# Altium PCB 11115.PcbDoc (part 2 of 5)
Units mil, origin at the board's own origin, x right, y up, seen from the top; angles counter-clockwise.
Board outline 4800 x 3500.1 mil, 4 copper layers (Top Layer, Layer 2, Layer 3, Bottom Layer), stack 61.6 mil thick; 316 components, 224 nets, 954 pads, 623 vias.
Unrouted connection lines stored in the file: 268.
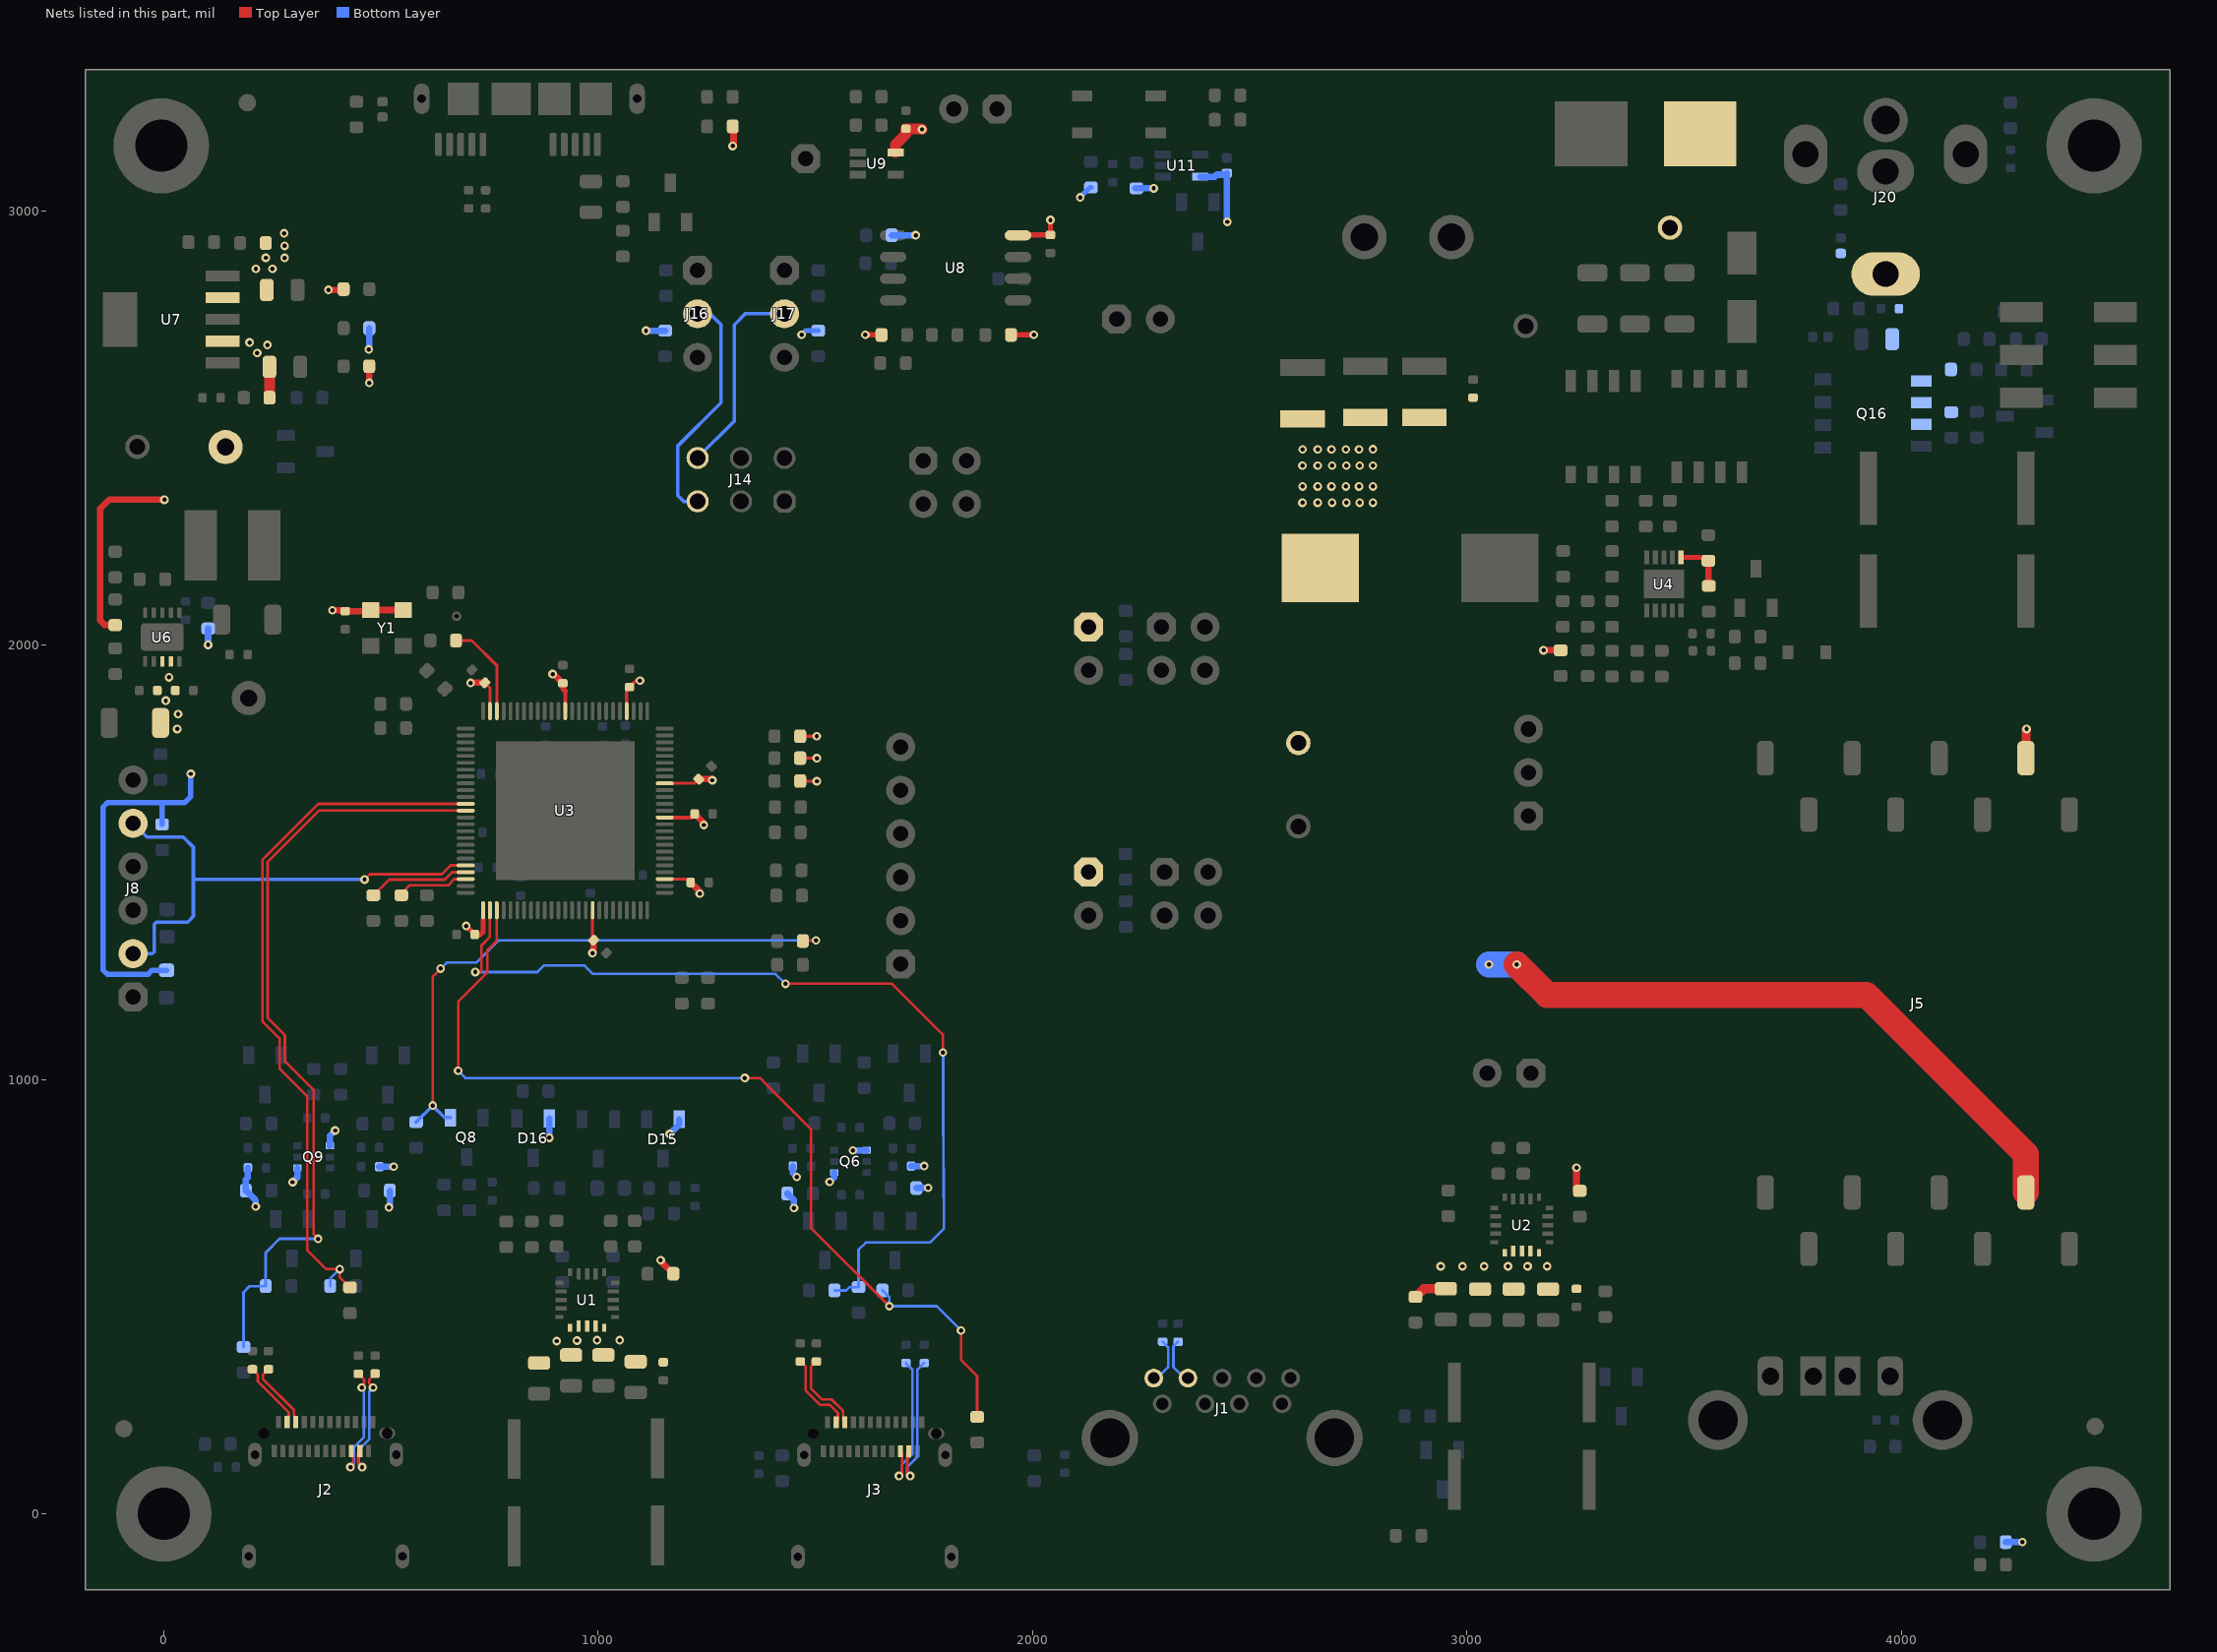
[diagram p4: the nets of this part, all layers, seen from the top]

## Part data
C1 C2 C3 C4: library part CAP1298, "Capacitor", Manufacturer 1="Panasonic Electronic Components", Manufacturer Part Number 1=EEE-FPC151XAP, Operating Temperature="-55C to 105C", Package=D8, Supplier Part Number 1=PCE4535CT-ND, Tolerance=20%, Voltage=16V
C5 C6 C7 C8 C16 C17 C18 C19: library part CAP0646, "Capacitor", Manufacturer 1="Taiyo Yuden", Manufacturer Part Number 1=JMK212BJ476MG-T, Operating Temperature="-55C to +85C", Package=0805, Supplier Part Number 1=587-1779-1-ND, Temperature Coeffcient=X5R, Tolerance=20%, Voltage=6.3V
C9 C10 C11 C12 C13 C14 C15 C20 C21 C22 C23 C24 C25 C26 C28 C30 C31 C32 C33 C35 C36 C38 C40 C43 C49 C55 C56 C57 C58 C60 C61 C62 C63 C64 C65 C66 C67 C68 C69 C70 C71 C72 C73 C74 C75 C76 C77 C78 C79 C80 C81 C82 C83 C84 C85 C86 C87 C88 C89 C90 C91 C92 C93 C96 C100 C101: library part CAP1337, "Capacitor", Manufacturer 1="TDK Corporation", Manufacturer Part Number 1=CGA2B3X7R1V104K050BB, Operating Temperature="-55C to 125C", Package=0402, Supplier Part Number 1=445-6901-1-ND, Temperature Coeffcient=X7R, Tolerance=10%, Voltage=35V
C27 C59 C94 C95: library part CAP0373, "Capacitor", Manufacturer 1="Wurth Electronics Inc", Manufacturer 2=Murata, Manufacturer 3="Taiyo Yuden", Manufacturer Part Number 1=885012107014, Manufacturer Part Number 2=GRM21BR61C106KE15L, Manufacturer Part Number 3=EMK212BJ106KG-T, Operating Temperature="+25C to +125C", Package=0805, Supplier Part Number 1=732-7624-1-ND, Temperature Coeffcient=X5R, Tolerance=10%, Voltage=16V
C29 C37 C39: library part CAP1998, "Capacitor", Manufacturer 1="WUERTH ELEKTRONIK", Manufacturer Part Number 1=885012108022, Operating Temperature="-55C to +85C", Package=1206, Temperature Coeffcient=X5R, Tolerance=10%, Voltage=50V
C34 C97: library part CAP1259, "Capacitor", Manufacturer 1="Samsung Electro-Mechanics America, Inc", Manufacturer Part Number 1=CL31B226KPHNNNE, Operating Temperature="-55C to +125C", Package=1206, Supplier Part Number 1=1276-2769-1-ND, Temperature Coeffcient=X7R, Tolerance=10%, Voltage=10V
C41 C42: library part CAP2007, "Capacitor", Manufacturer 1=KEMET, Manufacturer Part Number 1=EDT476M050S9MAA, Operating Temperature="-40°C ~ 125°C", Package=F, Supplier Part Number 1=80-EDT476M050S9MAA, Tolerance=20%, Voltage=50V
C44 C45: library part CAP2214, "Capacitor", Manufacturer 1="TDK Corporation", Manufacturer Part Number 1=CGA3E3X7R1H334K080AB, Operating Temperature="-55°C ~ 125°C", Package=0603, Supplier Part Number 1=445-174426-1-ND, Temperature Coeffcient=X7R, Tolerance=10%, Voltage=50V
C46 C47 C48: library part CAP0598, "Capacitor", Manufacturer 1="Taiyo Yuden", Manufacturer Part Number 1=LMK325BJ107MM-T, Operating Temperature="-55C to +85C", Package=1210, Supplier Part Number 1=587-1965-1-ND, Temperature Coeffcient=X5R, Tolerance=20%, Voltage=10V
C50: library part CAP0638, "Capacitor", Manufacturer 1="Taiyo Yuden", Manufacturer Part Number 1=LMK107BJ105KA-T, Operating Temperature="-55C to +85C", Package=0603, Supplier Part Number 1=587-2400-1-ND, Temperature Coeffcient=X5R, Tolerance=10%, Voltage=50V
C51: library part CAP1232, "Capacitor", Manufacturer 1=TDK, Manufacturer Part Number 1=C1608C0G1H392J080AA, Operating Temperature="-55C to +125C", Package=0603, Supplier Part Number 1=445-7399-1-ND, Temperature Coeffcient=C0G, Tolerance=5%, Voltage=50V
C52: library part CAP0088, "Capacitor", Manufacturer 1=KEMET, Manufacturer 2=Yageo, Manufacturer 3=Cal-Chip, Manufacturer 4=Panasonic, Manufacturer 5=TDK, Manufacturer 6="NIC Components", Manufacturer Part Number 1=C0603C330J5GACTU, Manufacturer Part Number 2=CC0603JRNP09BN330, Manufacturer Part Number 3=GMC10CG330J50NTLF, Manufacturer Part Number 4=ECU-V1H330JCV, Manufacturer Part Number 5=C1608C0G1H330J, Manufacturer Part Number 6=NMC0603NPO330J50TRPF, Manufacturer Part Number 7=ECJ-1VC1H330J, Operating Temperature="-55C to +125C", Package=0603, Supplier Part Number 1=399-1055-1-ND, Temperature Coeffcient=NP0, Tolerance=5%, Voltage=50V
C53: library part CAP1288, "Capacitor", Manufacturer 1="TDK Corporation", Manufacturer Part Number 1=C1608X5R1C475K080AC, Operating Temperature="-55C to +85C", Package=0603, Supplier Part Number 1=445-7478-1-ND, Temperature Coeffcient=X5R, Tolerance=10%, Voltage=16V
C54: library part CAP0413, "Capacitor", Manufacturer 1=Panasonic, Manufacturer Part Number 1=ECJ-1VC1H681J, Operating Temperature="-55C to +125C", Package=0603, Supplier Part Number 1=PCC2149TR-ND, Temperature Coeffcient=NP0, Tolerance=5%, Voltage=50V
C98: library part CAP1208, "Capacitor", Manufacturer 1=Murata, Manufacturer Part Number 1=GRM155R61A225KE95D, Operating Temperature="-55C to +85C", Package=0402, Temperature Coeffcient=X5R, Tolerance=10%, Voltage=10V
C99: library part CAP0603, "Capacitor", Manufacturer 1=AVX, Manufacturer Part Number 1=06033A471JAT2A, Operating Temperature="-55C to +125C", Package=0603, Supplier Part Number 1=478-6201-1-ND, Temperature Coeffcient=NP0, Tolerance=5%, Voltage=25V
D1 D2 D5 D6 D7 D8: library part DIODE1155, "LED", Forward Current=30mA, Manufacturer 1="Lite-On Inc", Manufacturer 2=Ledtech, Manufacturer Part Number 1=LTST-C191KGKT, Manufacturer Part Number 2=LT8A23-54-SB96-T5, Operating Temperature="-55C to +85C", Power=75mW, Reverse Voltage=5V, Supplier Part Number 1=160-1446-1-ND
D3: library part DIODE1204, Manufacturer 1="ON Semiconductor", Manufacturer Part Number 1=MM3Z5V1ST1G, Operating Temperature="-65C ~ 150C", Package="SC-76, SOD-323", Power=200mW, Supplier Part Number 1=MM3Z5V1ST1GOSCT-ND
D4: library part DIODE1259, Manufacturer 1="STMicroelectronics                                                                               STMicroelectronics", Manufacturer Part Number 1=SMA6T18AY, Operating Temperature="-55°C ~ 150°C", Package=DO-214AC_SMA, Power=600W, Reverse Voltage=15.3V, Supplier Part Number 1=497-11827-1-ND
D9: library part DIODE1056, "LED", Forward Current=20mA, Manufacturer 1=Lite-On, Manufacturer 2=Everlight, Manufacturer 4="Dongguan Zhiding Electronics Technology Co., LTD", Manufacturer Part Number 1=LTST-C193TBKT-5A, Manufacturer Part Number 2=19-21-BHC-ZL1M2TY-3T, Manufacturer Part Number 3=LTST-C190TBKT, Manufacturer Part Number 4=AL-S0603SRC-50-08-2, Operating Temperature="-20C to +80C", Package=0603, Power=76mW, Reverse Current=10uA, Reverse Voltage=5V, Supplier Part Number 1=160-1827-1-ND
D10: library part LED1073, "LED", Forward Current=20mA, Manufacturer 1="Lite-On Inc.", Manufacturer Part Number 1=LTST-C191KRKT, Package=0603, Supplier Part Number 1=160-1447-1-ND
D11 D12 D13 D14: library part DIODE1156, Forward Current=900mA, Manufacturer 1="Diodes Incorporated", Manufacturer Part Number 1=SBR160S23-7, Operating Temperature="-65°C ~ 150°C", Package=SOT23-3, Reverse Current="100µA @ 45V", Reverse Voltage=60V, Supplier Part Number 1=SBR160S23-7DICT-ND
D15 D16: library part DIODE0073, Forward Current=200mA, Manufacturer 1=Fairchild, Manufacturer Part Number 1=BAV99, Manufacturer Part Number 2=BAV99_NL, Operating Temperature="-55C to +150C", Package=SOT-23-3, Power=350mW, Reverse Current=2.5uA, Reverse Voltage=70V, Supplier Part Number 1=BAV99FSCT-ND
F1: library part FUSE1018, Manufacturer 1="Littelfuse Inc.", Manufacturer Part Number 1=0154010.DR, Operating Temperature="-55°C ~ 125°C", Package=2-SMD, Supplier Part Number 1=F1251DKR-ND, Voltage=125V
J1: library part CON1254, "Connector USB", Current=1.8A, Manufacturer 1="Wurth Electronics Inc", Manufacturer Part Number 1=692121030100, Supplier Part Number 1=732-3146-1-ND, Voltage=30V
J2 J3: library part CON1809, Current=5A, Manufacturer 1="Amphenol Commercial Products", Manufacturer Part Number 1=12401610E4#2A, Supplier Part Number 1=12401610E4#2ACT-ND
J4: library part CON0280, "Connector USB", Manufacturer 1="TE Connectivity AMP Connectors", Manufacturer 2="Dongguan Yang Ming Precision Plastic Hardware Electronics Co., Ltd. (ShenZhen YangMing)", Manufacturer Part Number 1=292303-1, Manufacturer Part Number 2=YM-02-04-B-18, Supplier Part Number 1=A31726-ND
J5: library part SKT1105, Manufacturer 1=3M, Manufacturer Part Number 1=963108-2000-AR-PR, Package="Dual 1X8 SM HDR", Supplier Part Number 1=3M9561CT-ND
J6 J9 J12 J18 J23: library part CON1108, Manufacturer 1=FCI, Manufacturer 4=Samtec, Manufacturer 5=Sullins, Manufacturer 6="SPC Technology", Manufacturer 8=Nextron, Manufacturer Part Number 1=77311-118-02LF, Manufacturer Part Number 2=68001-202HLF, Manufacturer Part Number 3=68000-202HLF, Manufacturer Part Number 4=TSW-102-07-G-S, Manufacturer Part Number 5=PBC02SAAN, Manufacturer Part Number 6=SPC20481, Manufacturer Part Number 7=TSW-102-07-F-S, Manufacturer Part Number 8=R-211-0211-0021-000, Manufacturer Part Number 9=TSW-102-07-S-S, Supplier Part Number 1=609-4434-ND
J7 J8: library part CON0438, Current=3A, Manufacturer 1=Sullins, Manufacturer 2=Nextron, Manufacturer Part Number 1=PEC06SAAN, Manufacturer Part Number 2=R-211-0611-0021-400, Supplier Part Number 1=S1012E-06-ND
J10 J13 J15: library part CON0464, Manufacturer 1=Samtec, Manufacturer Part Number 1=TSW-102-07-G-D, Supplier Part Number 1=SAM1028-02-ND
J11: library part CON1105, Manufacturer 1=FCI, Manufacturer 2=Nextron, Manufacturer Part Number 1=68000-103HLF, Manufacturer Part Number 2=R-211-0311-0021-000, Supplier Part Number 1=609-3461-ND
J14: library part CON1743, Manufacturer 1="Samtec Inc.", Manufacturer Part Number 1=TSW-102-07-G-T, Supplier Part Number 1=TSW-102-07-G-T-ND
J16 J17: library part CON1105, Manufacturer 1=FCI, Manufacturer Part Number 1=68000-103HLF, Supplier Part Number 1=609-3461-ND
J19: library part CON1738, Current=20A, Manufacturer 1="On Shore Technology Inc.", Manufacturer Part Number 1=OSTOQ025451, Supplier Part Number 1=ED2828-ND, Voltage=300V
J20: library part CON1784, Current=8A, Manufacturer 1="CUI Inc.", Manufacturer Part Number 1=PJ-063BH, Supplier Part Number 1=CP-063BH-ND, Voltage=24V
J21: library part CON1102, "CON HDR-2.54 Male 1x1 Gold 5.97MH TH VERT", Manufacturer 1="TE Connectivity", Manufacturer 2=Nextron, Manufacturer Part Number 1=5-146280-1, Manufacturer Part Number 2=211-0111-0021-400, Manufacturer Part Number 3=5-146868-1, Supplier Part Number 1=A107006-ND
J22: library part CON1341, "Connector USB", Current=1.8A, Manufacturer 1="Hirose Electric Co Ltd", Manufacturer Part Number 1=ZX360D-B-10P, Supplier Part Number 1=H11889CT-ND, Voltage=30V
L1: library part IND1556, Manufacturer 1="Wurth Electronics Inc.", Manufacturer Part Number 1=7443551200, Operating Temperature="-40°C ~ 155°C", Package=L12.8W12.8H6.2, Saturation Current=22A, Supplier Part Number 1=732-1125-1-ND, Test Frequency=100kHz
L2: library part IND1560, Manufacturer 1="Murata Electronics North America", Manufacturer Part Number 1=LQH5BPN1R5NT0L, Operating Temperature="-40°C ~ 125°C", Package=L5W5H2.2, RMS Current=3A, Saturation Current=5A, Supplier Part Number 1=490-7777-1-ND, Test Frequency=100kHz
LABEL1: library part 08-00028
Q1: library part TRA1333, Current=60A, Drain to Source Voltage=25V, Gate to Source Voltage=+20V/-16V, Manufacturer 1="Vishay / Siliconix", Manufacturer Part Number 1=SIRA24DP-T1-GE3, Operating Temperature="-55C to +150C", Package="PPAK SO-8", Power=62.5W, Supplier Part Number 1=SIRA24DP-T1-GE3CT-ND
Q2: library part TRA1334, Current=60A, Drain to Source Voltage=30V, Gate to Source Voltage=+20V/-16V, Manufacturer 1="Vishay Siliconix", Manufacturer Part Number 1=SIRA12BDP-T1-GE3, Operating Temperature="-55C to +150C", Package="PPAK SO-8", Power=38W, Supplier Part Number 1=SIRA12BDP-T1-GE3CT-ND
Q3 Q4 Q5 Q7 Q8 Q10 Q11 Q12 Q13 Q14: library part TRA1102, "Transistor MOS", Current=170mA, Drain to Source Voltage=60V, Gate to Source Voltage=20V, Manufacturer 1="Diodes Inc", Manufacturer Part Number 1=2N7002-7-F, Operating Temperature="-55C to +150C", Package=SOT-23-3, Power=370mW, Supplier Part Number 1=2N7002-FDICT-ND
Q6 Q9: library part TRA1232, "Transistor MOS Dual P+P SGDSGD", Current=300mA, Drain to Source Voltage=12V, Gate to Source Voltage=1.5V, Manufacturer 1="ON Semiconductor", Manufacturer Part Number 1=FDG6316P, Operating Temperature="-55°C ~ 150°C", Package=SC-88, Power=0.3W, Supplier Part Number 1=FDG6316PCT-ND
Q15: library part TRA0006, "Transistor Bipolar", Current=200mA, Manufacturer 1="Diodes Incorporated", Manufacturer 3=Fairchild, Manufacturer 4="Micro Commercial Components Corporation", Manufacturer 5="NXP Semiconductors", Manufacturer 6="ON Semiconductor", Manufacturer 9=STMicroelectronics, Manufacturer Part Number 1=MMBT3904-7, Manufacturer Part Number 2=MMBT3904-7-F, Manufacturer Part Number 3=MMBT3904, Manufacturer Part Number 4=MMBT3904-TP, Manufacturer Part Number 5=PMBT3904,215, Manufacturer Part Number 6=MMBT3904LT1G, Manufacturer Part Number 7=MMBT3904LT3G, Manufacturer Part Number 8=MMBT3904LT3, Operating Temperature="-55C to +150C", Package=SOT-23-3, Power=310mW, Supplier Part Number 1=MMBT3904DITR-ND, Supplier Part Number 10=497-2478-2-ND, Voltage=40V
Q16: library part TRA1208, "Transistor MOS", Current=17.7A, Drain to Source Voltage=-30V, Gate to Source Voltage=25V, Manufacturer 1="Infineon Technologies", Manufacturer Part Number 1=BSC060P03NS3EGATMA1, Operating Temperature="-55C to +150C", Package=PG-TDSON-8, Power=83W, Supplier Part Number 1=BSC060P03NS3EGATMA1CT-ND
R1 R2 R15 R16 R17 R18 R22 R23 R24 R25 R28 R30 R67 R68: library part RSMT0001, "Resistor", Manufacturer 1="NIC Components", Manufacturer 2=Panasonic, Manufacturer 4="Stackpole Electronics Inc", Manufacturer 5=Vishay, Manufacturer 7=Yageo, Manufacturer 8="KOA Speer", Manufacturer 9=ROHM, Manufacturer Part Number 1=NRC06Z0TRF, Manufacturer Part Number 2=ERJ-3GSY0R00V, Manufacturer Part Number 3=ERJ-3GEY0R00V, Manufacturer Part Number 4=RMCF0603ZT0R00, Manufacturer Part Number 5=CRCW06030000Z0EA, Manufacturer Part Number 6="RMCF 1/16 0 R", Manufacturer Part Number 7=RC0603JR-070RL, Manufacturer Part Number 8=RK73Z1JTTP, Manufacturer Part Number 9=MCR03EZPJ000, Operating Temperature="-55C to +155C", Package=0603, Power=1/10W
R3 R38 R46 R58 R59 R61: library part RES1130, Manufacturer 1=Panasonic, Manufacturer Part Number 1=ERJ-3EKF2201V, Operating Temperature="-55C to +155C", Package=0603, Power=1/10W, Supplier Part Number 1=P2.20KHCT-ND, Temperature Coeffcient=100ppm/C, Tolerance=1%, Voltage=75V
R4 R60 R66 R105: library part RSMT0138, Manufacturer 1=Panasonic, Manufacturer 2=Yageo, Manufacturer 3=ROHM, Manufacturer 4="Stackpole Electronics Inc", Manufacturer 6=Vishay, Manufacturer 8="TE Connectivity", Manufacturer Part Number 1=ERJ-3EKF1001V, Manufacturer Part Number 2=RC0603FR-071KL, Manufacturer Part Number 3=MCR03EZPFX1001, Manufacturer Part Number 4=RMCF0603FT1K00, Manufacturer Part Number 5="RMCF 1/16 1K 1% R", Manufacturer Part Number 6=CRCW06031K00FKEA, Manufacturer Part Number 7=RMCF1/161.0K1%TR, Manufacturer Part Number 8=1622866-1, Operating Temperature="-55C to +155C", Package=0603, Power=1/10W, Supplier Part Number 1=P1.00KHCT-ND, Temperature Coeffcient=100ppm/C, Tolerance=1%, Voltage=75V
R5 R12 R21 R26 R27 R29 R33 R34 R41 R42 R44 R45 R50 R52 R95 R97 R99 R100 R106 R111 R112 R118 R122 R124 R125: library part RSMT0625, Manufacturer 1=ROHM, Manufacturer 2=Vishay, Manufacturer 3="TE Connectivity", Manufacturer Part Number 1=MCR03EZPFX1002, Manufacturer Part Number 2=CRCW060310K0FKEA, Manufacturer Part Number 3=1622829-1, Operating Temperature="-55C to +155C", Package=0603, Power=1/10W, Supplier Part Number 1=RHM10.0KHCT-ND, Temperature Coeffcient=100ppm/C, Tolerance=1%, Voltage=75V
R6 R11: library part RES1169, Manufacturer 1=Panasonic, Manufacturer Part Number 1=ERJ-3EKF3302V, Operating Temperature="-55C to +155C", Package=0603, Power=1/10W, Supplier Part Number 1=P33.0KHCT-ND, Temperature Coeffcient=100ppm/C, Tolerance=1%, Voltage=75V
R7 R8 R9 R10 R35 R36 R49 R51: library part RSMT0001, Manufacturer 1=Panasonic, Manufacturer 3=ROHM, Manufacturer 4="Stackpole Electronics Inc", Manufacturer 6=Vishay, Manufacturer 7=Yageo, Manufacturer 8="KOA Speer", Manufacturer 9="NIC Components", Manufacturer Part Number 1=ERJ-3GSY0R00V, Manufacturer Part Number 2=ERJ-3GEY0R00V, Manufacturer Part Number 3=MCR03EZPJ000, Manufacturer Part Number 4=RMCF0603ZT0R00, Manufacturer Part Number 5="RMCF 1/16 0 R", Manufacturer Part Number 6=CRCW06030000Z0EA, Manufacturer Part Number 7=RC0603JR-070RL, Manufacturer Part Number 8=RK73Z1JTTP, Manufacturer Part Number 9=NRC06Z0TRF, Operating Temperature="-55C to +155C", Package=0603, Power=1/10W, Supplier Part Number 1=P0.0GTR-ND
R13 R14 R71 R72: library part RSMT0215, "Resistor", Manufacturer 1=Panasonic, Manufacturer 2="Stackpole Electronics Inc", Manufacturer Part Number 1=ERJ-3EKF1003V, Manufacturer Part Number 2=RMCF0603FT100K, Operating Temperature="-55C to +155C", Power=1/10W, Supplier Part Number 1=P100KHTR-ND, Temperature Coeffcient=100ppm/C, Voltage=75V
R19 R20 R96 R98 R113 R114: library part RSMT0627, Manufacturer 1=Panasonic, Manufacturer 2="Stackpole Electronics Inc", Manufacturer Part Number 1=ERJ-3EKF2003V, Manufacturer Part Number 2=RMCF0603FT200K, Operating Temperature="-55C to +155C", Package=0603, Power=1/10W, Supplier Part Number 1=P200KHCT-ND, Temperature Coeffcient=100ppm/C, Tolerance=1%, Voltage=75V
R31 R110 R119: library part RES1120, Manufacturer 1=Yageo, Manufacturer Part Number 1=RC0603FR-0712KL, Operating Temperature="-55C to +155C", Package=0603, Power=1/10W, Supplier Part Number 1=311-12.0KHRCT-ND, Temperature Coeffcient=100ppm/C, Tolerance=1%, Voltage=50V
R32: library part RES1137, "Resistor", Manufacturer 1=Panasonic, Manufacturer Part Number 1=ERJ-3EKF20R0V, Operating Temperature="-55C to +155C", Package=0603, Power=1/10W, Supplier Part Number 1=P20.0HCT-ND, Temperature Coeffcient=100ppm/C, Tolerance=1%, Voltage=75V
R37: library part RES1185, Manufacturer 1=Vishay, Manufacturer Part Number 1=CRCW0603470KFKEA, Operating Temperature="-55C to +155C", Package=0603, Power=1/10W, Supplier Part Number 1=541-470KHCT-ND, Temperature Coeffcient=100ppm/C, Tolerance=1%, Voltage=75V
R39: library part RSMT0309, Manufacturer 1=Panasonic, Manufacturer 2=Yageo, Manufacturer 4="Stackpole Electronics Inc", Manufacturer Part Number 1=ERJ-3EKF2002V, Manufacturer Part Number 2=9C06031A2002FKHFT, Manufacturer Part Number 3=RC0603FR-0720KL, Manufacturer Part Number 4=RMCF1/1620.0K1%TR, Manufacturer Part Number 5=9C06031A2002FKPFT, Operating Temperature="-55C to +155C", Package=0603, Power=1/10W, Supplier Part Number 1=P20.0KHCT-ND, Temperature Coeffcient=100ppm/C, Tolerance=1%, Voltage=50V
R40 R43 R103: library part RSMT0001, Manufacturer 1="NIC Components", Manufacturer 2=Panasonic, Manufacturer 4="Stackpole Electronics Inc", Manufacturer 5=Vishay, Manufacturer 7=Yageo, Manufacturer 8="KOA Speer", Manufacturer 9=ROHM, Manufacturer Part Number 1=NRC06Z0TRF, Manufacturer Part Number 2=ERJ-3GSY0R00V, Manufacturer Part Number 3=ERJ-3GEY0R00V, Manufacturer Part Number 4=RMCF0603ZT0R00, Manufacturer Part Number 5=CRCW06030000Z0EA, Manufacturer Part Number 6="RMCF 1/16 0 R", Manufacturer Part Number 7=RC0603JR-070RL, Manufacturer Part Number 8=RK73Z1JTTP, Manufacturer Part Number 9=MCR03EZPJ000, Operating Temperature="-55C to +155C", Package=0603, Power=1/10W
R47: library part RES1210, Manufacturer 1=Panasonic, Manufacturer Part Number 1=ERJ-3EKF8201V, Operating Temperature="-55C to +155C", Package=0603, Power=1/10W, Supplier Part Number 1=P8.20KHCT-ND, Temperature Coeffcient=100ppm/C, Tolerance=1%, Voltage=75V
R48: library part RSMT0309, Manufacturer 1=Yageo, Manufacturer 4="Stackpole Electronics Inc", Manufacturer 5=Panasonic, Manufacturer Part Number 1=9C06031A2002FKHFT, Manufacturer Part Number 2=RC0603FR-0720KL, Manufacturer Part Number 3=9C06031A2002FKPFT, Manufacturer Part Number 4=RMCF1/1620.0K1%TR, Manufacturer Part Number 5=ERJ-3EKF2002V, Operating Temperature="-55C to +155C", Package=0603, Power=1/10W, Supplier Part Number 1=311-20.0KHTR-ND, Temperature Coeffcient=100ppm/C, Tolerance=1%, Voltage=50V
R53 R115 R117 R120: library part RSMT0215, Manufacturer 1=Panasonic, Manufacturer 2="Stackpole Electronics Inc", Manufacturer 3="Rohm Semiconductor", Manufacturer 4="TE Connectivity", Manufacturer Part Number 1=ERJ-3EKF1003V, Manufacturer Part Number 2=RMCF0603FT100K, Manufacturer Part Number 3=MCR03EZPFX1003, Manufacturer Part Number 4=1622827-1, Operating Temperature="-55C to +155C", Package=0603, Power=1/10W, Supplier Part Number 1=P100KHTR-ND, Temperature Coeffcient=100ppm/C, Tolerance=1%, Voltage=75V
R54 R75 R82: library part RSMT0383, Manufacturer 1=Panasonic, Manufacturer Part Number 1=ERJ-3EKF4992V, Operating Temperature="-55C to +155C", Package=0603, Power=1/10W, Supplier Part Number 1=P49.9KHTR-ND, Temperature Coeffcient=100ppm/C, Tolerance=1%, Voltage=75V
R55: library part RES1052, Manufacturer 1=Vishay, Manufacturer Part Number 1=CRCW0603750RFKEA, Operating Temperature="-55C to +155C", Package=0603, Power=1/10W, Supplier Part Number 1=541-750HCT-ND, Temperature Coeffcient=100ppm/C, Tolerance=1%, Voltage=75V
R56 R76 R80: library part RSMT0665, Manufacturer 1=Yageo, Manufacturer Part Number 1=9C06031A4302FKHFT, Operating Temperature="-55C to +155C", Package=0603, Power=1/10W, Supplier Part Number 1=311-43.0KHDKR-ND, Temperature Coeffcient=100ppm/C, Tolerance=1%, Voltage=50V
R57 R62 R63 R64 R65 R102: library part RSMT0626, Manufacturer 1=Panasonic, Manufacturer 2="Stackpole Electronics Inc", Manufacturer Part Number 1=ERJ-3EKF3300V, Manufacturer Part Number 2=RMCF0603FT330R, Operating Temperature="-55C to +155C", Package=0603, Power=1/10W, Supplier Part Number 1=P330HCT-ND, Temperature Coeffcient=100ppm/C, Tolerance=1%, Voltage=75V
R69 R70 R73 R74: library part RES1566, Manufacturer 1="Vishay Dale", Manufacturer Part Number 1=CRCW06032R00FKEAHP, Operating Temperature="-55C to +155C", Package=0603, Power=1/10W, Supplier Part Number 1=541-2.00SCT-ND, Temperature Coeffcient=100ppm/C, Tolerance=1%, Voltage=75V
R77 R81: library part RSMT0788, Manufacturer 1=Yageo, Manufacturer Part Number 1=RC0603FR-07560RL, Operating Temperature="-55C to +155C", Package=0603, Power=1/10W, Supplier Part Number 1=311-560HRCT-ND, Temperature Coeffcient=100ppm/C, Tolerance=1%, Voltage=50V
R78 R79 R83 R84 R86 R87 R88 R89: library part RSMT0138, Manufacturer 1=Panasonic, Manufacturer 2=ROHM, Manufacturer 3="Stackpole Electronics Inc", Manufacturer 5=Vishay, Manufacturer 7=Yageo, Manufacturer 8="TE Connectivity", Manufacturer Part Number 1=ERJ-3EKF1001V, Manufacturer Part Number 2=MCR03EZPFX1001, Manufacturer Part Number 3=RMCF0603FT1K00, Manufacturer Part Number 4="RMCF 1/16 1K 1% R", Manufacturer Part Number 5=CRCW06031K00FKEA, Manufacturer Part Number 6=RMCF1/161.0K1%TR, Manufacturer Part Number 7=RC0603FR-071KL, Manufacturer Part Number 8=1622866-1, Operating Temperature="-55C to +155C", Package=0603, Power=1/10W, Supplier Part Number 1=P1.00KHCT-ND, Temperature Coeffcient=100ppm/C, Tolerance=1%, Voltage=75V
R85 R90 R91 R92 R93 R94: library part RSMT0215, "Resistor", Manufacturer 1=Panasonic, Manufacturer 2="Stackpole Electronics Inc", Manufacturer 3="Rohm Semiconductor", Manufacturer 4="TE Connectivity", Manufacturer Part Number 1=ERJ-3EKF1003V, Manufacturer Part Number 2=RMCF0603FT100K, Manufacturer Part Number 3=MCR03EZPFX1003, Manufacturer Part Number 4=1622827-1, Operating Temperature="-55C to +155C", Package=0603, Power=1/10W, Supplier Part Number 1=P100KHTR-ND, Temperature Coeffcient=100ppm/C, Tolerance=1%, Voltage=75V
R101: library part RES1707, Manufacturer 1=Yageo, Manufacturer Part Number 1=RC0603FR-072K55L, Operating Temperature="-55C to +155C", Package=0603, Power=1/10W, Supplier Part Number 1=311-2.55KHRCT-ND, Temperature Coeffcient=100ppm/C, Tolerance=1%
R104: library part RES1137, Manufacturer 1=Panasonic, Manufacturer Part Number 1=ERJ-3EKF20R0V, Operating Temperature="-55C to +155C", Package=0603, Power=1/10W, Supplier Part Number 1=P20.0HCT-ND, Temperature Coeffcient=100ppm/C, Tolerance=1%, Voltage=75V
R107 R108: library part RSMT0456, Manufacturer 1=Panasonic, Manufacturer 2=Yageo, Manufacturer 3=SET, Manufacturer Part Number 1=ERJ-3EKF10R0V, Manufacturer Part Number 2=RC0603FR-0710RL, Manufacturer Part Number 3=RMCF1/1610.01%TR, Operating Temperature="-55C to +155C", Package=0603, Power=1/10W, Supplier Part Number 1=P10.0HTR-ND, Temperature Coeffcient=100ppm/C, Tolerance=1%, Voltage=75V
R109: library part RES1540, Manufacturer 1="Panasonic Electronic Components", Manufacturer Part Number 1=ERJ-3EKF8662V, Operating Temperature="-55°C ~ 155°C", Package=0603, Power=1/10W, Supplier Part Number 1=P86.6KHCT-ND, Temperature Coeffcient=±100ppm/°C, Tolerance=1%
R116: library part RSMT0590, Manufacturer 1="Stackpole Electronics Inc", Manufacturer Part Number 1="RMC 1/16 500 5% R", Operating Temperature="-55C to +155C", Package=0603, Power=1/10W, Supplier Part Number 1=RMC1/165005%R-ND, Temperature Coeffcient=100ppm/C, Tolerance=5%, Voltage=50V
R121: library part RES1404, Manufacturer 1=Yageo, Manufacturer Part Number 1=RC0603FR-07300RL, Operating Temperature="-55C to +155C", Package=0603, Power=1/10W, Supplier Part Number 1=311-300HRCT-ND, Temperature Coeffcient=100ppm/C, Tolerance=1%
SW1: library part SWITCH1002, "SWITCH SLIDE DPDT 6VDC 0.3A SMT", Contact Rating @ Voltage="0.3A @ 6VDC", Current=300mA, Manufacturer="C&K Components", Manufacturer 1=C&K, Manufacturer 3="SWITECH ELECTRONICS", Manufacturer 4="Switech Electronics Co. Ltd", Manufacturer Part Number=JS202011SCQN, Manufacturer Part Number 3=CUS-12TB, Manufacturer Part Number 4=MS-22D17-G2-W, Operating Temperature="-40C to +85C", Supplier Part Number 1=401-2002-1-ND, Voltage=6V
SW2: library part SWITCH1072, "Switch", Current=50mA, Manufacturer 1="C&K Components", Manufacturer Part Number 1="PTS810 SJM 250 SMTR LFS", Operating Temperature="-40°C ~ 85°C", Supplier Part Number 1=CKN10502CT-ND, Voltage=16V
TP1 TP7: library part MISC0027, Manufacturer 1=Keystone, Manufacturer Part Number 1=5000, Supplier Part Number 1=36-5000-ND
TP2 TP6 TP8: library part MISC0026, Manufacturer 1=Keystone, Manufacturer Part Number 1=5001, Supplier Part Number 1=36-5001-ND
TP3: library part CON1282, Manufacturer 1="Keystone Electronics", Manufacturer Part Number 1=5003, Supplier Part Number 1=5003K-ND
TP4: library part CON2017, "Test Point"
TP5: library part MISC0119, Manufacturer 1=Keystone, Manufacturer 2="FuZhou XiXiang", Manufacturer Part Number 1=5004, Manufacturer Part Number 2=CONN00197B01, Supplier Part Number 1=36-5004-ND
U1 U2: library part MIC8861, "UCS2114 Dual USB port power", Manufacturer 1="Microchip Technology", Manufacturer Part Number 1=UCS2114-1A-V/LX
U3: library part MIC8839, Manufacturer 1="Microchip Technology", Manufacturer Part Number 1=USB7252/KDX
U4: library part MIC5997, InputVoltageRangeMax=30, InputVoltageRangeMin=4.5, Manufacturer 1=Microchip, Manufacturer Part Number 1=MCP19035-BAABE/MF, PackageType=DFN, PackageWidth=3x3x0.9mm, QuiescentCurrent=6, Supplier Part Number 1=MCP19035-BAABE/MF-ND, SwitchingFrequency=600, TempRange="-40C to +125C"
U5: library part MIC2289, Manufacturer 1="Microchip Technology", Manufacturer Part Number 1=MCP111T-475E/TT, NominalResetVoltage="1.87, 2.29, 2.59, 2.86, 2.87, 3.03, 4.31, 4.56", PackageType=SOT-23, PackageWidth=1.3mm, TempRange="-40C to +125C", TypicalSupplyCurrent=1
U6: library part MIC7256, InputVoltageRangeMax=5.5, InputVoltageRangeMin=2.7, Manufacturer 1="Microchip Technology", Manufacturer Part Number 1=MIC23201YML-TR, PackageType=VDFN, PackageWidth=3x3x0.9mm, QuiescentCurrent=1.15, Supplier Part Number 1=576-4159-1-ND, SwitchingFrequency=2000, TempRange="-40C to +125C"
U7: library part MIC7428, Manufacturer 1=Microchip, Manufacturer Part Number 1=MCP1825T-ADJE/DC, Supplier Part Number 1=MCP1825T-ADJE/DCCT-ND
U8: library part MIC6476, "SQI Serial Flash", Manufacturer 1="Microchip Technology", Manufacturer Part Number 1=SST26VF016B-104I/SM, MaxClockFreq="104 MHz", OpVoltMax=3.6, OpVoltMin=2.3, PackageType=SOIJ, PackageWidth=.208in, Supplier Part Number 1=SST26VF016B-104I/SM-ND, TempRange="-40C to +85C"
U9 U11: library part IC1251, "Single Schmitt Trigger Inverter", Manufacturer 1=NXP, Operating Temperature="-40C to +125C,", Package=SC-70-5, Supplier Part Number 1=771-74LVC1G14GW-G
U10: library part MIC7416, Manufacturer 1="Microchip Technology", Manufacturer Part Number 1=MIC803-29D4VM3-TR, Supplier Part Number 1=576-3806-1-ND
Y1: library part MIC8253, Manufacturer 1="Microchip Technology", Manufacturer Part Number 1=DSC1001CI2-025.0000, Supplier Part Number 1=DSC1001CI2-025.0000CT-ND

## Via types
v1: diameter 20, hole 10, Top Layer to Bottom Layer, tented both sides, 576 vias
v2: diameter 23, hole 11, Top Layer to Bottom Layer, 36 vias
v3: diameter 20, hole 12, Top Layer to Bottom Layer, 7 vias
v4: diameter 27.56, hole 11.81, Top Layer to Bottom Layer, 4 vias

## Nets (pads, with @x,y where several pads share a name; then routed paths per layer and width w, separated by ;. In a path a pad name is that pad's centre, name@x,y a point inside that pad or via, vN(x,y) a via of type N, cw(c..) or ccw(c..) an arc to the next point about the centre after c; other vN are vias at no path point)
3V3_BRD: C21.1 C22.1 C23.1 C24.1 C25.1 C30.1 C31.1 C32.1 C38.2 C56.2 C94.2 C100.1 D7.1 D15.2 D16.2 J5.7 J9.1 J12.1 R26.2 R27.2 R29.2 R50.2 R52.2 R98.1 R105.2 R107.1 R108.1 R109.2 R118.2 R120.2 R121.2 R122.1 R124.1 TP3.1 U3.26 U3.42 U3.53 U3.62 U3.67 U3.79 U3.88 U3.99 U7.4 U8.8 U11.5 Y1.1 Y1.4 | length 4666.9
  Top Layer w7: U3.26@735.21,1369.26 U3.26@735.21,1390 ; C30.1@739.19,1913.79 750.95,1902.03 U3.99@750.95,1848.27 ; U3.42@987.17,1390 987.17,1320.28 C21.1@989.52,1317.93 ; U3.53@1153.32,1461.65 1205.1,1461.65 C23.1@1213.06,1453.7 ; U3.67@1153.32,1682.13 1153.65,1682.46 1221.69,1682.46 1231.32,1692.09 C25.1@1231.62,1691.8 ; R26.2@1465.18,1680.16 1471.94,1686.92 v1(1503.44,1686.92) v1@1503.44,1686.42 ; R27.2@1465.18,1740.16 1503.24,1740.16 v1@1503.83,1739.56 ; R29.2@1465.18,1790.55 v1(1503.24,1790.55)
  Top Layer w8: U3.79@1065.91,1848.27 1065.91,1897.68 C32.1@1072.15,1903.91 1086.81,1918.57 v1(1096.39,1918.57)
  Top Layer w9: U3.88@924.18,1848.27 924.18,1894.61 ; U3.62@1153.32,1603.39 1213.95,1603.39 C24.1@1222.31,1611.74
  Top Layer w12: v1(696.28,1353.63) C22.1@715.91,1334 728.54,1334 735.21,1340.67 U3.26@735.21,1369.26 ; C31.1@918.59,1912.63 918.59,1900.21 924.18,1894.61 ; v1(1615.11,2714.67) R50.2@1652.27,2714.67 ; R52.2@1950.58,2714.67 v1(2002.94,2714.67) ; U8.8@1966.45,2943.98 1967.28,2944.81 C56.2@2041.31,2944.81 v1(2041.31,2979.22)
  Top Layer w15: R122.1@-111.77,2046.44 -136.02,2046.44 -146.63,2057.06 -146.63,2314.37 -126,2335 v1(1.43,2335) ; v1(388.05,2080.41) 412.61,2080.41 414.57,2078.45 C38.2@417.75,2078.45 473.92,2078.45 Y1.1@476.54,2081.07 Y1.4@551.35,2081.07 ; v1(473.02,2604.09) D7.1@473.02,2642.37 ; v1(706.54,1913.29) 707.04,1913.79 C30.1@739.19,1913.79 ; v1(895.23,1933.5) 897.72,1933.5 C31.1@918.59,1912.63 ; v1(987.05,1291.35) 989.52,1293.82 989.52,1317.93 C21.1@989.52,1320.86 ; C23.1@1213.06,1453.7 1233.92,1432.83 v1(1233.92,1427.99) ; C24.1@1222.31,1611.74 1243.17,1590.87 v1(1243.17,1586.07) ; C25.1@1231.62,1691.8 1260.34,1691.8 v1(1263.01,1689.13)
  Top Layer w60: v1(3115,1265) 3115,1264.8 3184.8,1195 3920,1195 4287.22,827.78 J5.7@4287.22,740
  Bottom Layer w12: R98.1@-3.84,1587.54 -3.84,1637.5 ; R124.1@6.64,1251.5 -26.75,1251.5 -35.74,1242.5 -130,1242.5 -140,1252.5 -140,1627.5 -130,1637.5 -3.84,1637.5 ; v1(62.13,1703.98) 62.13,1651.93 47.7,1637.5 -3.84,1637.5 ; v1(1468.26,2714.67) 1477.85,2724.26 R107.1@1506.65,2724.26 ; v1(2109.66,3031.18) 2132.5,3054.02 R121.2@2134.47,3054.02
  Bottom Layer w15: v1@473.02,2682.18 R105.2@473.02,2730 ; v1(887.66,866.02) 887.84,866.2 D16.2@887.84,910.58 ; v1(1110.14,2724.26) R108.1@1154.3,2724.26 ; v1(1164.71,874.45) 1186.79,896.53 D15.2@1186.79,908.45 ; R118.2@1676,2943.98 v1(1731.05,2943.98) ; v1(2109.66,3031.18) v1@2111.63,3031.18 ; R120.2@2236.46,3052.2 v1(2279.15,3052.2) ; U11.5@2386.67,3078.82 2419.62,3078.82 2424.35,3083.54 C100.1@2447.14,3083.54 ; C100.1@2447.45,3086.69 2447.45,2975.91 v1(2448.63,2974.72)
  Bottom Layer w60: v1@3050.85,1264.8 3051.05,1265 v1(3115,1265)
  other v1: 3050.85,1264.9 1503.53,1739.86 471.9,2681.27 211.96,2866.49 250.36,2866.49 234.83,2892.08 278.24,2891.8 278.24,2919.67 277.03,2948.53
5V_BRD: C5.2 C6.1 C7.2 C8.1 C13.2 C16.2 C17.1 C18.1 C19.2 C20.2 C34.2 C35.2 C36.2 C46.2 C47.2 C48.2 C49.2 C60.1 C74.2 C75.2 C76.2 C77.2 C95.2 D5.1 J5.10 L1.2 Q6.1 Q6.4 Q9.1 Q9.4 R3.1 R5.1 R12.1 R43.2 R58.1 R61.1 R78.2 R79.2 R83.2 R84.2 R106.1 R111.2 TP7.1 U1.6 U1.7 U1.8 U1.9 U1.10 U2.6 U2.7 U2.8 U2.9 U2.10 U6.8 U6.9 U7.2 U9.5 | length 1046.4
  Top Layer w15: v1(379.19,2818.13) 412.09,2818.13 D5.1@413.97,2820 ; v1(1144,584.31) 1144,581.7 R5.1@1172.96,552.74 ; v1(1309.87,3149.38) 1309.87,3150.73 1311.83,3152.69 1311.83,3192.73 R58.1@1309.87,3194.68 ; v1(3176.65,1988.39) R43.2@3215.84,1988.39 ; R12.1@3252.3,743.74 v1(3252.3,797.22) ; v1@4287.22,1805.63 v1(4288.68,1807.09)
  Top Layer w20: J5.10@4287.22,1740 v1@4287.22,1805.63
  Top Layer w22: R3.1@2881.65,499.53 2900.51,518.4 C16.2@2951.65,518.4
  Top Layer w25: R106.1@243.41,2570 C95.2@243.41,2640.98 ; U9.5@1684.95,3134.72 1684.95,3152.75 1708.58,3176.37 C60.1@1708.58,3189.13 1744.32,3189.13 v1(1745.61,3187.84)
  Bottom Layer w15: v1(102.06,2000.95) 102.06,2038.31 R111.2@102.23,2038.47 ; C77.2@193.65,796.73 193.65,774.73 188.94,770.02 R84.2@188.94,744.31 211.65,721.61 v1(211.65,707.77) ; v1(296.65,763.73) 307.74,774.83 Q9.1@307.74,796.14 ; Q9.4@382.55,847.32 382.55,870.63 v1(394.65,882.73) ; C76.2@496.02,799.26 529.14,799.26 v1(529.38,799.5) ; v1(518.45,705.79) 520.43,707.77 R83.2@520.43,744.31 ; R79.2@1435.64,737.54 1450.83,722.35 v1(1450.83,704.39) ; C75.2@1448.31,800.8 1448.31,784.93 v1(1457.49,775.75) ; v1(1532.86,764.13) 1543.35,774.62 Q6.4@1543.35,785.78 ; v1(1586.65,836.96) Q6.1@1618.15,836.96 ; C74.2@1720.75,800.8 v1(1750.73,800.8) ; R78.2@1732.56,750.41 1759.52,750.41 v1(1759.65,750.54) ; R61.1@4240.81,-65 v1(4279.15,-65)
  other v1: 904.51,397.85 951.44,398.95 997.44,399.86 1049.44,399.86 2939.8,569.96 2989.8,569.96 3039.8,569.96 3094.8,569.96 3139.8,569.96 3184.8,569.96 31.05,1807.12 32.98,1841.45 4.71,1872.41 12.17,1926.21 2621.43,2328.3 2656.63,2328.25 2689.74,2328.28 2722.81,2328.25 2753.3,2328.26 2783.91,2328.25 2621.72,2365.69 2656.63,2365.7 2688.27,2365.7 2721.63,2365.7 2751.63,2365.72 2783.91,2365.74 2621.43,2413.69 2656.63,2413.64 2689.74,2413.68 2722.81,2413.64 2753.3,2413.66 2783.91,2413.64 2621.72,2451.08 2656.63,2451.1 2688.27,2451.1 2721.63,2451.1 2751.63,2451.12 2783.91,2451.14 215.25,2673.01 238.59,2691.33 197.59,2696.94
5VL: C53.2 R53.2 U4.6 | length 123.3
  Top Layer w12: U4.6@3493.07,2202.08 3546.53,2202.08 C53.2@3556.07,2192.54
  Top Layer w15: C53.2@3556.07,2192.54 3556.07,2137.56 R53.2@3557.07,2136.56
25MHZ: R36.2 U3.98 | length 227.7
  Top Layer w7: R36.2@665.91,2010.83 R36.2@669.29,2007.45 ; R36.2@672.67,2010.83 709.26,2010.83 766.7,1953.39 U3.98@766.7,1848.27
BASIC_CC1_P1: R2.1 R73.2 U3.12 | length 1655.2
  Top Layer w6: R2.1@428.68,521.28 404.93,545.02 v1(404.93,563.44) 373.88,563.44 330.08,607.24 330.08,961.72 266.75,1025.05 266.75,1094.37 227.16,1133.96 227.16,1505.88 356.16,1634.88 U3.12@695.05,1634.88
  Bottom Layer w6: R73.2@383.28,524.83 383.28,541.79 v1(404.93,563.44)
BASIC_CC1_P2: R68.1 R70.2 U3.27 | length 2119.8
  Top Layer w6: v1(717.07,1247.52) 728.51,1247.52 731.33,1250.34 731.33,1309.05 750.95,1328.68 U3.27@750.95,1390 ; v1(1431.38,1220.48) 1677.01,1220.48 1793.65,1103.83 v1(1793.67,1062.36)
  Bottom Layer w6: v1(717.07,1247.52) 860.08,1247.52 874.94,1262.38 969.15,1262.38 988.15,1243.38 1408.48,1243.38 v1(1431.38,1220.48) ; R70.2@1544.38,514.58 1571,514.58 1578.64,522.22 R68.1@1599.46,522.22 1599.46,608.31 1616.01,624.86 1764.05,624.86 1795.8,656.61 1794.32,940.11 1794.32,1061.72 v1(1793.67,1062.36)
BASIC_CC2_P1: R67.1 R74.2 U3.13 | length 1814
  Top Layer w6: v1(355.16,633.31) 345.15,643.33 345.15,975.68 278.75,1042.08 278.75,1099.34 278.06,1100.03 278.06,1103.36 239.16,1142.26 239.16,1500.91 357.39,1619.13 U3.13@695.05,1619.13
  Bottom Layer w6: R67.1@183.65,384.25 183.65,510.38 197.81,524.54 R74.2@234.62,524.54 234.62,601.18 266.75,633.31 v1(355.16,633.31)
BASIC_CC2_P2: R1.1 R69.2 U3.28 | length 2202.6
  Top Layer w6: v1(677.7,1020.29) 677.7,1179.74 745.3,1247.34 745.3,1298.53 766.7,1319.93 U3.28@766.7,1390 ; v1(1337.71,1003.66) 1372.69,1003.66 1388.15,988.2 1388.15,987.61 1489.95,885.8 1489.95,658.76 v1(1670.36,478.36) ; v1(1835.45,422.23) 1835.45,354.44 1872.65,317.25 R1.1@1872.65,223.21
  Bottom Layer w6: v1(677.7,1020.29) 694.33,1003.66 v1(1337.71,1003.66) ; R69.2@1654.61,514.58 1670.36,498.84 v1(1670.36,478.36) 1779.33,478.36 v1(1835.45,422.23)
C_USB3DN_TX3_N: C68.2 J1.8 | length 106.9
  Bottom Layer w6: C68.2@2335.17,396.49 2324.54,385.86 2324.54,337.92 2349.92,312.53 J1.8@2357.91,312.53
C_USB3DN_TX3_P: C69.2 J1.9 | length 107.8
  Bottom Layer w6: J1.9@2279.17,312.53 2287.15,312.53 2312.54,337.92 2312.54,383.67 C69.2@2299.72,396.49
C_USB3DN_TXD1A_N: C10.2 J2.A3 | length 157.8
  Top Layer w6: C10.2@241.01,333.11 228.6,320.71 228.6,309.99 299.91,238.69 299.91,225.88 300.84,224.94 300.84,214.49 J2.A3@303.75,211.58
C_USB3DN_TXD1A_P: C9.2 J2.A2 | length 157.8
  Top Layer w6: C9.2@204.2,333.11 216.6,320.71 216.6,305.02 287.91,233.72 287.91,225.88 286.97,224.94 286.97,214.49 J2.A2@284.06,211.58
C_USB3DN_TXD1B_N: C11.2 J2.B3 | length 278.3
  Top Layer w6: v1(429.76,107.76) 435.54,113.51 435.54,140.81 J2.B3@431.7,144.65 ; C11.2@447.94,322.58 461.23,309.29 461.23,296.12 v1(455.8,290.69)
  Bottom Layer w6: v1(429.76,107.76) 437.26,115.26 437.26,153.33 460.75,176.82 460.75,285.74 v1(455.8,290.69)
C_USB3DN_TXD1B_P: C12.2 J2.B2 | length 278.1
  Top Layer w6: J2.B2@451.39,144.65 447.54,140.81 447.54,116.88 v1(456.66,107.76) ; v1@478.31,294.17 474.8,297.69 474.8,298.56 473.23,300.12 473.23,309.66 C12.2@486.52,322.95
  Bottom Layer w6: v1(456.66,107.76) 449.26,115.16 449.26,148.36 472.75,171.85 472.75,280.77 474.8,282.82 474.8,283.69 v1(481.8,290.69)
C_USB3DN_TXD2A_N: C15.2 J3.A3 | length 190.6
  Top Layer w6: C15.2@1502.38,350.92 1489.95,338.49 1489.95,288.59 1515.2,263.35 1537.83,263.35 1563.91,237.27 1563.91,214.77 J3.A3@1567.75,210.93
C_USB3DN_TXD2A_P: C14.2 J3.A2 | length 190.6
  Top Layer w6: C14.2@1465.53,350.92 1477.95,338.49 1477.95,337.92 1477.95,283.62 1510.23,251.35 1532.86,251.35 1551.91,232.3 1551.91,214.77 J3.A2@1548.06,210.93
C_USB3DN_TXD2B_N: C67.2 J3.B3 | length 343.3
  Top Layer w6: v1(1692.54,87.23) 1697.86,87.23 1699.54,88.92 1699.54,140.16 J3.B3@1695.7,144
  Bottom Layer w6: v1(1692.54,87.23) 1699.54,94.23 1699.54,113.23 1723.31,137 1723.31,332.71 C67.2@1708.65,347.37
C_USB3DN_TXD2B_P: C66.2 J3.B2 | length 343.8
  Top Layer w6: J3.B2@1715.39,144 1711.54,140.16 1711.54,88.92 1713.23,87.23 v1(1718.54,87.23)
  Bottom Layer w6: v1(1718.54,87.23) 1711.54,94.23 1711.54,108.26 1735.31,132.03 1735.31,332.08 C66.2@1750.73,347.5
CFG_BC_EN: J14.3 J16.2 | length 550.2
  Bottom Layer w8: J14.3@1228.96,2331.29 1196.92,2331.29 1183.76,2344.45 1183.76,2459.39 1283.29,2558.93 1283.29,2738.09 1258.25,2763.13 J16.2@1228.96,2763.13
CFG_NON_REM: J14.6 J17.2 | length 467.5
  Bottom Layer w8: J14.6@1228.96,2431.29 1313.6,2515.93 1313.6,2737.89 1338.83,2763.13 J17.2@1428.96,2763.13
CFG_STRAP1: J8.2 J8.5 U3.21 | length 1173.5
  Top Layer w6: v1(462.34,1460.7) 474.53,1472.89 639.89,1472.89 660.15,1493.15 U3.21@695.05,1493.15
  Bottom Layer w8: J8.2@-70.85,1290 -70.37,1289.52 -26.2,1289.52 -21.51,1294.2 -21.51,1357.81 -16.82,1362.5 54.72,1362.5 68.09,1375.87 68.09,1460.7 ; J8.5@-70.85,1590 -38.87,1558.02 45.24,1558.02 68.09,1535.16 68.09,1460.7 ; v1(462.34,1460.7) 68.09,1460.7
CFG_STRAP2: R19.1 U3.22 | length 234.6
  Top Layer w6: R19.1@482.45,1424.39 518.45,1460.38 647.37,1460.38 664.39,1477.4 U3.22@695.05,1477.4
CFG_STRAP3: R20.1 U3.23 | length 166.2
  Top Layer w6: R20.1@546.95,1424.39 546.95,1428.89 565.29,1447.23 654.38,1447.23 668.81,1461.65 U3.23@695.05,1461.65
DC_IN: C27.2 C28.1 C55.2 F1.1 J20.1 Q16.1 Q16.2 Q16.3 R33.2 R34.2 TP1.1
DP1_DISCHARGE: Q8.1 R18.1 R85.2 | length 1351.2
  Top Layer w6: v1(619.23,940.2) 619.23,1237.33 v1(637.45,1255.55) ; R18.1@1471.27,1319.11 1500.2,1319.11 v1(1501.37,1320.28)
  Bottom Layer w6: v1(637.45,1255.55) 651.01,1269.11 719.6,1269.11 770.77,1320.28 v1(1501.37,1320.28)
  Bottom Layer w8: R85.2@580.95,901.92 v1(619.23,940.2) 619.23,939.24 646.18,912.28 Q8.1@659.98,912.28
